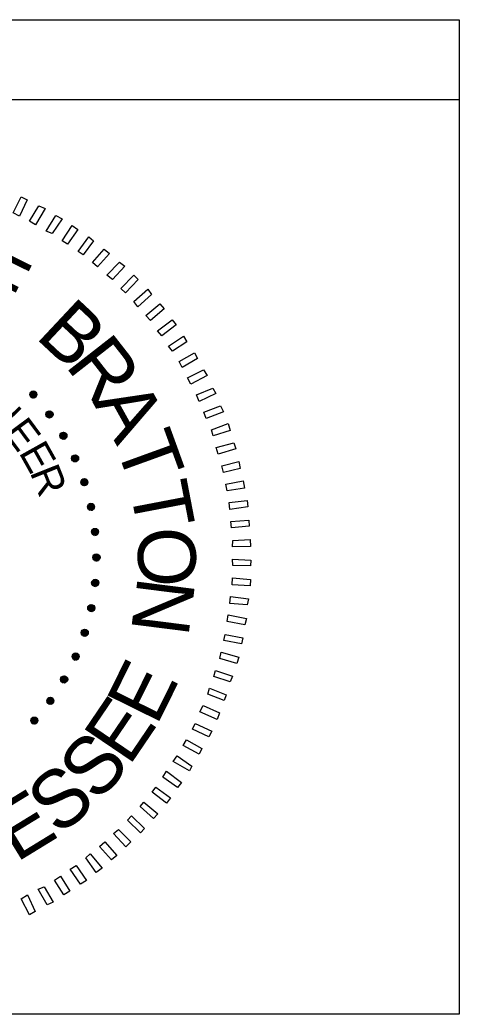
# Model space of a CAD drawing. Extents: x 1577619 to 1828281, y 483481 to 598136.
# Drawn here: x 1710698 to 1712905, y 511185 to 516185 of the extents above; entities that cross this region are included whole.
import ezdxf

# ---------------------------------------------------------------- set-up
doc = ezdxf.new("R2010")
doc.units = 0
doc.layers.add('DESIGN - SHEET - Linework', color=7, linetype='Continuous')
doc.layers.add('Volkert Engineer Seal', color=7, linetype='Continuous')

msp = doc.modelspace()

# ---------------------------------------------------------------- linework, layer by layer
at = {"layer": 'DESIGN - SHEET - Linework'}
msp.add_line((1706804.8, 515784.6), (1712904.8, 515784.6), dxfattribs=at)
msp.add_lwpolyline([(1712904.8, 511184.6), (1706804.8, 511184.6), (1706804.8, 516184.6), (1712904.8, 516184.6)], close=True, dxfattribs=at)
at = {"layer": 'Volkert Engineer Seal'}
for p, q in [((1710747.8, 514301.7), (1710766.3, 514318.4)), ((1710747.9, 514298.4), (1710769.6, 514318)), ((1710748.5, 514295.5), (1710772.5, 514317.1)), ((1710748.6, 514305.8), (1710762.2, 514318.1)), ((1710749.4, 514292.9), (1710774.9, 514315.9)), ((1710750.7, 514290.6), (1710777, 514314.4)), ((1710752.2, 514288.6), (1710778.9, 514312.6)), ((1710754, 514286.8), (1710780.5, 514310.6)), ((1710756.1, 514285.3), (1710781.8, 514308.4)), ((1710758.5, 514284), (1710782.8, 514305.9)), ((1710761.3, 514283.1), (1710783.4, 514303.1)), ((1710764.5, 514282.6), (1710783.6, 514299.8)), ((1710768.5, 514282.8), (1710783, 514295.8)), ((1710774.8, 514285), (1710780.1, 514289.8)), ((1710828.8, 514200.8), (1710852.5, 514218)), ((1710829, 514204.1), (1710849.2, 514218.8)), ((1710829, 514197.9), (1710855.2, 514216.9)), ((1710829.7, 514195.2), (1710857.5, 514215.4)), ((1710830.2, 514208.1), (1710845, 514218.9)), ((1710830.7, 514192.8), (1710859.4, 514213.7)), ((1710832.1, 514190.7), (1710861.1, 514211.7)), ((1710833.7, 514188.7), (1710862.5, 514209.6)), ((1710835.6, 514186.9), (1710863.5, 514207.2)), ((1710837.9, 514185.4), (1710864.3, 514204.6)), ((1710840.5, 514184.2), (1710864.6, 514201.7)), ((1710843.6, 514183.4), (1710864.5, 514198.5)), ((1710847.6, 514183.1), (1710863.4, 514194.6)), ((1710854.2, 514184.7), (1710859.9, 514188.9)), ((1710899, 514095.3), (1710924.4, 514110)), ((1710899, 514092.4), (1710927, 514108.5)), ((1710899.4, 514089.7), (1710929.1, 514106.8)), ((1710899.6, 514098.6), (1710921.2, 514111.1)), ((1710900.2, 514087.2), (1710930.9, 514104.9)), ((1710901.2, 514102.5), (1710917.1, 514111.6)), ((1710901.2, 514084.9), (1710932.3, 514102.8)), ((1710902.6, 514082.8), (1710933.5, 514100.5)), ((1710904.4, 514080.8), (1710934.3, 514098.1)), ((1710906.4, 514079.1), (1710934.7, 514095.4)), ((1710908.9, 514077.6), (1710934.8, 514092.5)), ((1710912, 514076.4), (1710934.3, 514089.3)), ((1710915.9, 514075.8), (1710932.9, 514085.5)), ((1710922.6, 514076.7), (1710928.7, 514080.2)), ((1710957.5, 513980.1), (1710987, 513993.3)), ((1710957.6, 513977.4), (1710989, 513991.4)), ((1710957.8, 513983.1), (1710984.6, 513995)), ((1710958.1, 513974.9), (1710990.5, 513989.3)), ((1710958.8, 513986.3), (1710981.6, 513996.4)), ((1710959, 513972.5), (1710991.8, 513987)), ((1710960.1, 513970.2), (1710992.6, 513984.7)), ((1710960.8, 513989.9), (1710977.5, 513997.4)), ((1710961.7, 513968.1), (1710993.2, 513982.1)), ((1710963.5, 513966.2), (1710993.4, 513979.4)), ((1710965.9, 513964.4), (1710993.1, 513976.5)), ((1710968.8, 513962.9), (1710992.3, 513973.4)), ((1710972.6, 513961.9), (1710990.5, 513969.8)), ((1710979.3, 513962.1), (1710985.8, 513965)), ((1711003.8, 513859.7), (1711036.4, 513870.3)), ((1711004, 513862.4), (1711034.7, 513872.4)), ((1711004.1, 513857.1), (1711037.8, 513868.1)), ((1711004.6, 513865.3), (1711032.5, 513874.3)), ((1711004.6, 513854.6), (1711038.8, 513865.7)), ((1711005.6, 513852.2), (1711039.4, 513863.2)), ((1711005.9, 513868.4), (1711029.7, 513876.1)), ((1711006.9, 513850), (1711039.7, 513860.7)), ((1711008.3, 513871.8), (1711025.7, 513877.5)), ((1711008.5, 513847.9), (1711039.6, 513858)), ((1711010.7, 513845.9), (1711039, 513855.1)), ((1711013.4, 513844.1), (1711037.9, 513852.1)), ((1711017.1, 513842.6), (1711035.7, 513848.7)), ((1711023.8, 513842.2), (1711030.6, 513844.3)), ((1711040.4, 513746.2), (1711064.9, 513751.4)), ((1711043.2, 513749.4), (1711061.1, 513753.2)), ((1711037.4, 513735.2), (1711072.1, 513742.5)), ((1711037.5, 513737.8), (1711071, 513744.9)), ((1711037.7, 513732.6), (1711072.8, 513740.1)), ((1711037.9, 513740.5), (1711069.5, 513747.2)), ((1711038.4, 513730.2), (1711073.2, 513737.6)), ((1711038.8, 513743.3), (1711067.5, 513749.4)), ((1711039.5, 513727.8), (1711073.2, 513735)), ((1711040.9, 513725.5), (1711072.8, 513732.3)), ((1711042.8, 513723.3), (1711072, 513729.5)), ((1711045.3, 513721.3), (1711070.5, 513726.6)), ((1711048.9, 513719.4), (1711068, 513723.5)), ((1711055.5, 513718.2), (1711062.5, 513719.7)), ((1711057.9, 513610.4), (1711093.1, 513614.1)), ((1711057.9, 513607.9), (1711093.6, 513611.6)), ((1711058.2, 513613), (1711092.3, 513616.6)), ((1711058.3, 513605.4), (1711093.7, 513609.1)), ((1711058.9, 513615.6), (1711091, 513619)), ((1711059.1, 513602.9), (1711093.4, 513606.5)), ((1711060.1, 513618.3), (1711089.3, 513621.4)), ((1711060.3, 513600.5), (1711092.8, 513603.9)), ((1711062, 513621.1), (1711086.8, 513623.7)), ((1711062, 513598.1), (1711091.6, 513601.2)), ((1711065.1, 513624), (1711083.3, 513625.9)), ((1711064.3, 513595.8), (1711089.9, 513598.5)), ((1711067.6, 513593.6), (1711087.1, 513595.6)), ((1711074.1, 513591.7), (1711081.1, 513592.4)), ((1711064.9, 513481.7), (1711100.8, 513481.7)), ((1711065.1, 513484.2), (1711100.6, 513484.2)), ((1711065.1, 513479.2), (1711100.7, 513479.2)), ((1711065.6, 513476.6), (1711100.1, 513476.6)), ((1711065.7, 513486.8), (1711100, 513486.8)), ((1711066.5, 513474.1), (1711099.2, 513474.1)), ((1711066.7, 513489.3), (1711099, 513489.3)), ((1711067.9, 513471.5), (1711097.8, 513471.5)), ((1711068.2, 513491.8), (1711097.5, 513491.8)), ((1711070, 513469), (1711095.7, 513469)), ((1711070.4, 513494.4), (1711095.3, 513494.4)), ((1711073.1, 513466.5), (1711092.6, 513466.5)), ((1711073.7, 513496.9), (1711092, 513496.9)), ((1711079.3, 513463.9), (1711086.4, 513463.9)), ((1711058.6, 513352.9), (1711094, 513349.2)), ((1711058.7, 513355.5), (1711094.4, 513351.7)), ((1711058.9, 513350.3), (1711093.2, 513346.7)), ((1711059.2, 513358), (1711094.5, 513354.3)), ((1711060, 513360.4), (1711094.1, 513356.8)), ((1711061.3, 513362.9), (1711093.4, 513359.5)), ((1711063, 513365.2), (1711092.2, 513362.2)), ((1711065.5, 513367.5), (1711090.3, 513364.9)), ((1711069, 513369.7), (1711087.3, 513367.8)), ((1711059.5, 513347.7), (1711092, 513344.3)), ((1711060.7, 513345), (1711090.3, 513341.9)), ((1711062.4, 513342.3), (1711088, 513339.6)), ((1711065.2, 513339.5), (1711084.7, 513337.4)), ((1711071.2, 513336.3), (1711078.2, 513335.5)), ((1711038.9, 513225.5), (1711072.7, 513218.3)), ((1711039, 513228.1), (1711073.8, 513220.7)), ((1711039.3, 513230.6), (1711074.4, 513223.1)), ((1711039.3, 513222.8), (1711071.3, 513216)), ((1711040.1, 513233), (1711074.8, 513225.6)), ((1711040.2, 513220), (1711069.4, 513213.8)), ((1711041.2, 513235.4), (1711074.7, 513228.2)), ((1711041.7, 513217.1), (1711066.8, 513211.7)), ((1711042.7, 513237.7), (1711074.3, 513230.9)), ((1711044.2, 513214), (1711063.3, 513209.9)), ((1711044.7, 513239.8), (1711073.3, 513233.7)), ((1711047.3, 513241.9), (1711071.7, 513236.7)), ((1711049.7, 513210.2), (1711056.7, 513208.7)), ((1711051.1, 513243.7), (1711069, 513239.8)), ((1711006.1, 513103.4), (1711038.9, 513092.7)), ((1711006.2, 513100.7), (1711037.3, 513090.6)), ((1711006.4, 513105.9), (1711040.2, 513094.9)), ((1711007, 513108.4), (1711041.1, 513097.3)), ((1711008, 513110.7), (1711041.7, 513099.8)), ((1711009.3, 513113), (1711042, 513102.4)), ((1711011.1, 513115.1), (1711041.8, 513105.1)), ((1711013.3, 513117), (1711041.2, 513108)), ((1711016.1, 513118.8), (1711039.9, 513111.1)), ((1711020.1, 513120.2), (1711037.5, 513114.5)), ((1711006.8, 513097.8), (1711035.1, 513088.6)), ((1711007.9, 513094.7), (1711032.4, 513086.8)), ((1711010.1, 513091.4), (1711028.7, 513085.3)), ((1711015.2, 513087), (1711022, 513084.8)), ((1710976.3, 513000.6), (1710993.1, 512993.2)), ((1710960.5, 512982.6), (1710990.3, 512969.4)), ((1710960.7, 512985.3), (1710992.2, 512971.3)), ((1710960.7, 512979.8), (1710988, 512967.6)), ((1710961.2, 512987.9), (1710993.7, 512973.4)), ((1710961.6, 512976.6), (1710985.1, 512966.1)), ((1710962.1, 512990.3), (1710994.9, 512975.7)), ((1710963.3, 512992.5), (1710995.7, 512978.1)), ((1710963.4, 512973), (1710981.2, 512965.1)), ((1710964.9, 512994.6), (1710996.2, 512980.6)), ((1710966.8, 512996.5), (1710996.3, 512983.4)), ((1710968, 512968.2), (1710974.5, 512965.3)), ((1710969.2, 512998.2), (1710996, 512986.3)), ((1710972.3, 512999.6), (1710995.1, 512989.5)), ((1710902.6, 512867.2), (1710928.5, 512852.2)), ((1710902.7, 512870.1), (1710931, 512853.7)), ((1710903.1, 512872.7), (1710933, 512855.5)), ((1710903.1, 512863.9), (1710925.4, 512851.1)), ((1710903.9, 512875.2), (1710934.8, 512857.4)), ((1710904.5, 512860.2), (1710921.5, 512850.4)), ((1710905.1, 512877.5), (1710936.2, 512859.5)), ((1710906.5, 512879.6), (1710937.2, 512861.8)), ((1710908.3, 512881.5), (1710938, 512864.3)), ((1710908.7, 512854.9), (1710914.8, 512851.3)), ((1710910.4, 512883.2), (1710938.4, 512867)), ((1710913, 512884.6), (1710938.4, 512870)), ((1710916.2, 512885.7), (1710937.8, 512873.3)), ((1710920.3, 512886.3), (1710936.2, 512877.1)), ((1710833.1, 512761.3), (1710857.2, 512743.7)), ((1710833.2, 512758), (1710854, 512742.9)), ((1710833.4, 512764.2), (1710859.8, 512745)), ((1710834.2, 512766.8), (1710862.1, 512746.5)), ((1710834.2, 512754.1), (1710850.1, 512742.6)), ((1710835.2, 512769.1), (1710864, 512748.2)), ((1710836.6, 512771.3), (1710865.6, 512750.2)), ((1710838.3, 512773.2), (1710866.9, 512752.3)), ((1710840.2, 512774.9), (1710868, 512754.7)), ((1710842.5, 512776.4), (1710868.6, 512757.4)), ((1710845.2, 512777.5), (1710868.9, 512760.3)), ((1710848.5, 512778.3), (1710868.7, 512763.7)), ((1710852.7, 512778.4), (1710867.5, 512767.7)), ((1710837.8, 512748.4), (1710843.5, 512744.2)), ((1710752.6, 512660), (1710771.8, 512642.7)), ((1710752.8, 512663.2), (1710775, 512643.3)), ((1710753.2, 512656), (1710767.8, 512642.9)), ((1710753.5, 512666.1), (1710777.7, 512644.2)), ((1710754.5, 512668.6), (1710780.1, 512645.5)), ((1710755.8, 512670.8), (1710782.2, 512647)), ((1710757.4, 512672.8), (1710784, 512648.8)), ((1710759.2, 512674.5), (1710785.6, 512650.8)), ((1710761.4, 512676), (1710786.8, 512653.1)), ((1710763.8, 512677.3), (1710787.8, 512655.6)), ((1710766.6, 512678.1), (1710788.4, 512658.5)), ((1710769.9, 512678.6), (1710788.5, 512661.9)), ((1710774.1, 512678.2), (1710787.7, 512666)), ((1710756.2, 512650), (1710761.4, 512645.2))]:
    msp.add_line(p, q, dxfattribs=at)
for points in [[(1710664.8, 515214.2), (1710704.8, 515294.2), (1710734.8, 515280.2), (1710696.8, 515198.2)], [(1710746.8, 515172.2), (1710792.8, 515250.2), (1710824.8, 515236.2), (1710776.8, 515154.2)], [(1710830.8, 515122.2), (1710878.8, 515200.2), (1710910.8, 515184.2), (1710860.8, 515110.2)], [(1710910.8, 515074.2), (1710960.8, 515150.2), (1710988.8, 515130.2), (1710936.8, 515056.2)], [(1710990.8, 515020.2), (1711044.8, 515094.2), (1711068.8, 515074.2), (1711016.8, 515002.2)], [(1711062.8, 514964.2), (1711120.8, 515032.2), (1711148.8, 515010.2), (1711088.8, 514942.2)], [(1711134.8, 514900.2), (1711198.8, 514966.2), (1711224.8, 514946.2), (1711162.8, 514878.2)], [(1711204.8, 514834.2), (1711270.8, 514900.2), (1711292.8, 514878.2), (1711228.8, 514812.2)], [(1711270.8, 514768.2), (1711340.8, 514830.2), (1711358.8, 514804.2), (1711290.8, 514742.2)], [(1711330.8, 514698.2), (1711400.8, 514756.2), (1711422.8, 514732.2), (1711354.8, 514672.2)], [(1711388.8, 514620.2), (1711462.8, 514676.2), (1711482.8, 514650.2), (1711410.8, 514596.2)], [(1711444.8, 514544.2), (1711520.8, 514594.2), (1711536.8, 514566.2), (1711464.8, 514518.2)], [(1711498.8, 514466.2), (1711574.8, 514510.2), (1711590.8, 514482.2), (1711512.8, 514436.2)], [(1711540.8, 514384.2), (1711620.8, 514424.2), (1711638.8, 514396.2), (1711556.8, 514352.2)], [(1711584.8, 514298.2), (1711666.8, 514332.2), (1711682.8, 514306.2), (1711598.8, 514266.2)], [(1711622.8, 514212.2), (1711706.8, 514244.2), (1711720.8, 514214.2), (1711634.8, 514180.2)], [(1711660.8, 514122.2), (1711744.8, 514154.2), (1711754.8, 514120.2), (1711668.8, 514092.2)], [(1711684.8, 514034.2), (1711772.8, 514058.2), (1711782.8, 514028.2), (1711694.8, 514000.2)], [(1711712.8, 513942.2), (1711798.8, 513964.2), (1711804.8, 513928.2), (1711720.8, 513908.2)], [(1711732.8, 513850.2), (1711820.8, 513866.2), (1711826.8, 513830.2), (1711738.8, 513816.2)], [(1711748.8, 513758.2), (1711840.8, 513768.2), (1711842.8, 513736.2), (1711752.8, 513722.2)], [(1711758.8, 513662.2), (1711848.8, 513668.2), (1711850.8, 513638.2), (1711760.8, 513630.2)], [(1711768.8, 513566.2), (1711854.8, 513572.2), (1711856.8, 513536.2), (1711766.8, 513534.2)], [(1711766.8, 513472.2), (1711858.8, 513468.2), (1711856.8, 513438.2), (1711768.8, 513440.2)], [(1711766.8, 513378.2), (1711856.8, 513370.2), (1711854.8, 513338.2), (1711764.8, 513344.2)], [(1711756.8, 513284.2), (1711846.8, 513272.2), (1711840.8, 513242.2), (1711752.8, 513250.2)], [(1711744.8, 513192.2), (1711836.8, 513174.2), (1711828.8, 513142.2), (1711738.8, 513158.2)], [(1711728.8, 513094.2), (1711818.8, 513076.2), (1711810.8, 513046.2), (1711722.8, 513064.2)], [(1711708.8, 513004.2), (1711798.8, 512980.2), (1711788.8, 512948.2), (1711702.8, 512972.2)], [(1711680.8, 512912.2), (1711766.8, 512884.2), (1711754.8, 512856.2), (1711672.8, 512882.2)], [(1711650.8, 512824.2), (1711734.8, 512790.2), (1711724.8, 512762.2), (1711642.8, 512794.2)], [(1711618.8, 512736.2), (1711700.8, 512700.2), (1711688.8, 512666.2), (1711602.8, 512704.2)], [(1711578.8, 512646.2), (1711662.8, 512608.2), (1711646.8, 512578.2), (1711564.8, 512618.2)], [(1711534.8, 512564.2), (1711612.8, 512520.2), (1711598.8, 512492.2), (1711518.8, 512536.2)], [(1711488.8, 512484.2), (1711562.8, 512432.2), (1711550.8, 512408.2), (1711468.8, 512454.2)], [(1711434.8, 512406.2), (1711510.8, 512350.2), (1711490.8, 512324.2), (1711416.8, 512376.2)], [(1711380.8, 512326.2), (1711454.8, 512272.2), (1711434.8, 512246.2), (1711362.8, 512300.2)], [(1711320.8, 512250.2), (1711390.8, 512192.2), (1711368.8, 512168.2), (1711302.8, 512228.2)], [(1711258.8, 512182.2), (1711324.8, 512118.2), (1711304.8, 512096.2), (1711238.8, 512160.2)], [(1711192.8, 512112.2), (1711254.8, 512050.2), (1711230.8, 512026.2), (1711168.8, 512092.2)], [(1711124.8, 512050.2), (1711184.8, 511982.2), (1711158.8, 511960.2), (1711098.8, 512028.2)], [(1711050.8, 511990.2), (1711110.8, 511918.2), (1711080.8, 511896.2), (1711028.8, 511970.2)], [(1710980.8, 511932.2), (1711032.8, 511856.2), (1711002.8, 511838.2), (1710950.8, 511914.2)], [(1710902.8, 511878.2), (1710948.8, 511802.2), (1710918.8, 511784.2), (1710872.8, 511858.2)], [(1710820.8, 511824.2), (1710864.8, 511748.2), (1710834.8, 511734.2), (1710790.8, 511812.2)], [(1710736.8, 511784.2), (1710774.8, 511700.2), (1710746.8, 511684.2), (1710704.8, 511764.2)]]:
    msp.add_lwpolyline(points, close=True, dxfattribs=at)
for centre in [(1710765.7, 514300.5), (1710846.7, 514201), (1710916.9, 514093.7), (1710975.4, 513979.6), (1711021.8, 513860), (1711055.3, 513736.2), (1711075.8, 513609.6), (1711082.9, 513481.5), (1711076.5, 513353.4), (1711056.8, 513226.7), (1711024, 513102.7), (1710978.4, 512982.8), (1710920.5, 512868.3), (1710851, 512760.6), (1710770.6, 512660.6)]:
    msp.add_circle(centre, 17.9, dxfattribs=at)

# ---------------------------------------------------------------- texts
for s, height, rotation, p in [('E', 290, 333.8187, (1710419.2, 514792.1)), ('B', 290, 316.8615, (1710770.6, 514589.5)), ('R', 290, 308.03, (1710921.7, 514446.4)), ('N', 150, 314.1127, (1710508.9, 514216.6)), ('A', 290, 299.0695, (1711062.3, 514263)), ('E', 150, 306.6691, (1710612.5, 514110.1)), ('T', 290, 289.9633, (1711175.1, 514050.9)), ('E', 150, 299.2252, (1710690.4, 514009.3)), ('R', 150, 291.7813, (1710746.7, 513909.5)), ('T', 290, 280.8571, (1711249.1, 513834.4)), ('O', 290, 271.7509, (1711287.2, 513629.8)), ('N', 290, 262.7904, (1711291.6, 513391)), ('E', 290, 63.6692, (1711384.8, 512630)), ('E', 290, 55.854, (1711246.6, 512427.2)), ('S', 290, 47.7827, (1711086.5, 512244.7)), ('S', 290, 39.5247, (1710892.7, 512076.6)), ('E', 290, 31.5283, (1710679.4, 511944.7))]:
    msp.add_text(s, height=height, rotation=rotation, dxfattribs=at).set_placement(p)

doc.saveas('drawing.dxf')
